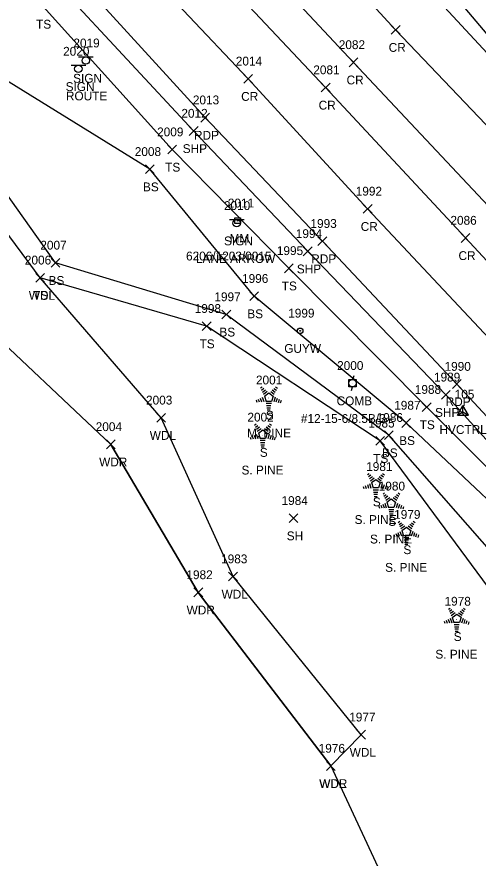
# Model space of a CAD drawing. Extents: x 1623612 to 1625808, y 621345 to 627748.
# Drawn here: x 1624252.1 to 1624356.5, y 626606.1 to 626796.7 of the extents above; entities that cross this region are included whole.
import ezdxf

# ---------------------------------------------------------------- set-up
doc = ezdxf.new("R2010")
doc.units = 0
for name, color, linetype in [('C_A', 7, 'Continuous'), ('C_I', 7, 'Continuous'), ('CPSM', 7, 'Continuous'), ('L_A', 7, 'Continuous'), ('L_C', 7, 'Continuous'), ('L_I', 7, 'Continuous'), ('L_TIC', 7, 'Continuous'), ('LAWA', 7, 'Continuous'), ('LELB', 7, 'Continuous'), ('LSOGP', 7, 'Continuous'), ('LTC', 7, 'Continuous'), ('P_A', 7, 'Continuous'), ('P_I', 7, 'Continuous'), ('P_TIC', 7, 'Continuous'), ('PET', 7, 'Continuous'), ('PRC', 7, 'Continuous'), ('PSP', 7, 'Continuous'), ('S_A', 7, 'Continuous'), ('S_C', 7, 'Continuous'), ('S_I', 7, 'Continuous'), ('SRM', 7, 'Continuous'), ('SSGN', 7, 'Continuous'), ('U_A', 7, 'Continuous'), ('U_C', 7, 'Continuous'), ('U_I', 7, 'Continuous'), ('UP', 7, 'Continuous'), ('UPGW', 7, 'Continuous')]:
    doc.layers.add(name, color=color, linetype=linetype)

msp = doc.modelspace()

# ---------------------------------------------------------------- linework, layer by layer
at = {"layer": 'CPSM'}
for p, q in [((1624351.85, 626706.52), (1624353.1, 626708.68)), ((1624354.35, 626706.52), (1624353.1, 626708.68)), ((1624353.1, 626707.24), (1624353.1, 626708.68)), ((1624351.85, 626706.52), (1624353.1, 626707.24)), ((1624351.85, 626706.52), (1624354.35, 626706.52)), ((1624353.1, 626707.24), (1624353.1, 626707.24)), ((1624353.1, 626707.24), (1624354.35, 626706.52))]:
    msp.add_line(p, q, dxfattribs=at)
at = {"layer": 'L_TIC'}
for points in [[(1624286.3, 626765.67), (1624288.3, 626767.67)], [(1624288.3, 626765.67), (1624286.3, 626767.67)], [(1624281.24, 626761.21), (1624283.24, 626763.21)], [(1624283.24, 626761.21), (1624281.24, 626763.21)], [(1624259.87, 626740.01), (1624261.87, 626742.01)], [(1624261.87, 626740.01), (1624259.87, 626742.01)], [(1624312.68, 626738.77), (1624314.68, 626740.77)], [(1624314.68, 626738.77), (1624312.68, 626740.77)], [(1624256.42, 626736.63), (1624258.42, 626738.63)], [(1624258.42, 626736.63), (1624256.42, 626738.63)], [(1624256.42, 626736.63), (1624258.42, 626738.63)], [(1624258.42, 626736.63), (1624256.42, 626738.63)], [(1624304.85, 626732.46), (1624306.85, 626734.46)], [(1624306.85, 626732.46), (1624304.85, 626734.46)], [(1624298.54, 626728.32), (1624300.54, 626730.32)], [(1624300.54, 626728.32), (1624298.54, 626730.32)], [(1624294.08, 626725.66), (1624296.08, 626727.66)], [(1624296.08, 626725.66), (1624294.08, 626727.66)], [(1624343.9, 626707.33), (1624345.9, 626709.33)], [(1624345.9, 626707.33), (1624343.9, 626709.33)], [(1624283.79, 626704.91), (1624285.79, 626706.91)], [(1624285.79, 626704.91), (1624283.79, 626706.91)], [(1624339.23, 626703.74), (1624341.23, 626705.74)], [(1624341.23, 626703.74), (1624339.23, 626705.74)], [(1624335.32, 626700.97), (1624337.32, 626702.97)], [(1624337.32, 626700.97), (1624335.32, 626702.97)], [(1624272.4, 626698.89), (1624274.4, 626700.89)], [(1624274.4, 626698.89), (1624272.4, 626700.89)], [(1624333.38, 626699.7), (1624335.38, 626701.7)], [(1624335.38, 626699.7), (1624333.38, 626701.7)], [(1624313.74, 626682.15), (1624315.74, 626684.15)], [(1624315.74, 626682.15), (1624313.74, 626684.15)], [(1624300.06, 626668.94), (1624302.06, 626670.94)], [(1624302.06, 626668.94), (1624300.06, 626670.94)], [(1624292.2, 626665.35), (1624294.2, 626667.35)], [(1624294.2, 626665.35), (1624292.2, 626667.35)], [(1624329.05, 626633.11), (1624331.05, 626635.11)], [(1624331.05, 626633.11), (1624329.05, 626635.11)], [(1624322.19, 626626.03), (1624324.19, 626628.03)], [(1624324.19, 626626.03), (1624322.19, 626628.03)], [(1624322.19, 626626.03), (1624324.19, 626628.03)], [(1624324.19, 626626.03), (1624322.19, 626628.03)]]:
    msp.add_lwpolyline(points, dxfattribs=at)
at = {"layer": 'LAWA'}
for points in [[(1624323.19, 626627.03), (1624330.05, 626634.11), (1624301.06, 626669.94), (1624284.79, 626705.91), (1624257.42, 626737.63), (1624223.02, 626784.04), (1624205.61, 626785.75)], [(1624323.19, 626627.03), (1624293.2, 626666.35), (1624273.4, 626699.89), (1624242.34, 626729.15), (1624205.61, 626785.75)]]:
    msp.add_lwpolyline(points, dxfattribs=at)
at = {"layer": 'LELB'}
for points in [[(1624382.88, 626625.35), (1624396.56, 626644.22), (1624396.84, 626651.57), (1624378.77, 626674.51), (1624344.9, 626708.33), (1624313.68, 626739.77), (1624287.3, 626766.67), (1624258.07, 626799.06), (1624230.36, 626827.29), (1624202.86, 626857.54), (1624181.4, 626879.71), (1624161.07, 626904.67)], [(1624380.03, 626635.67), (1624388.85, 626639.75), (1624394.9, 626646.05), (1624375.51, 626671.51), (1624340.23, 626704.74), (1624305.85, 626733.46), (1624282.24, 626762.21), (1624242, 626787.06), (1624227.53, 626819.4), (1624211.45, 626808.79)], [(1624388.85, 626639.75), (1624369.38, 626664.3), (1624336.32, 626701.97), (1624299.54, 626729.32), (1624260.87, 626741.01), (1624233.8, 626779.17), (1624211.45, 626808.79)], [(1624379.66, 626643.16), (1624364.81, 626659.38), (1624334.38, 626700.7), (1624295.08, 626726.66), (1624257.42, 626737.63)]]:
    msp.add_lwpolyline(points, dxfattribs=at)
at = {"layer": 'LSOGP'}
msp.add_lwpolyline([(1624185.05, 626801.31), (1624205.61, 626785.75), (1624242.34, 626729.15), (1624273.4, 626699.89), (1624293.2, 626666.35), (1624323.19, 626627.03), (1624337.94, 626595.4), (1624375.16, 626557.28)], dxfattribs=at)
at = {"layer": 'LTC'}
for p, q in [((1624307.29, 626712.67), (1624307.65, 626712.93)), ((1624307.5, 626712.2), (1624308.03, 626712.59)), ((1624307.71, 626711.74), (1624308.42, 626712.25)), ((1624307.92, 626711.27), (1624308.8, 626711.91)), ((1624309.58, 626711.86), (1624310.39, 626711.27)), ((1624309.95, 626712.21), (1624310.63, 626711.72)), ((1624310.32, 626712.56), (1624310.87, 626712.16)), ((1624310.69, 626712.91), (1624311.11, 626712.6)), ((1624306.33, 626709.95), (1624306.48, 626709.48)), ((1624306.78, 626710.16), (1624306.99, 626709.51)), ((1624307.24, 626710.38), (1624307.51, 626709.54)), ((1624307.69, 626710.6), (1624308.02, 626709.58)), ((1624308.15, 626710.82), (1624309.16, 626711.55)), ((1624308.15, 626710.82), (1624308.53, 626709.62)), ((1624309.16, 626711.55), (1624310.16, 626710.83)), ((1624310.16, 626710.83), (1624309.76, 626709.62)), ((1624310.59, 626710.55), (1624310.26, 626709.51)), ((1624311.04, 626710.3), (1624310.75, 626709.42)), ((1624311.48, 626710.05), (1624311.25, 626709.32)), ((1624309.76, 626709.62), (1624308.53, 626709.62)), ((1624309.73, 626709.12), (1624308.58, 626709.12)), ((1624309.64, 626708.62), (1624308.65, 626708.62)), ((1624309.56, 626708.12), (1624308.73, 626708.12)), ((1624311.93, 626709.8), (1624311.74, 626709.23)), ((1624309.48, 626707.62), (1624308.8, 626707.62)), ((1624305.93, 626704.27), (1624306.29, 626704.53)), ((1624306.14, 626703.81), (1624306.67, 626704.19)), ((1624309.33, 626704.51), (1624309.75, 626704.21)), ((1624306.35, 626703.34), (1624307.06, 626703.85)), ((1624306.56, 626702.87), (1624307.44, 626703.51)), ((1624306.79, 626702.42), (1624307.8, 626703.15)), ((1624306.79, 626702.42), (1624307.17, 626701.23)), ((1624307.8, 626703.15), (1624308.8, 626702.43)), ((1624308.22, 626703.47), (1624309.03, 626702.88)), ((1624308.8, 626702.43), (1624308.4, 626701.23)), ((1624308.59, 626703.82), (1624309.27, 626703.32)), ((1624308.96, 626704.16), (1624309.51, 626703.76)), ((1624304.97, 626701.55), (1624305.12, 626701.08)), ((1624305.42, 626701.77), (1624305.63, 626701.12)), ((1624305.88, 626701.98), (1624306.15, 626701.15)), ((1624306.33, 626702.2), (1624306.66, 626701.18)), ((1624308.4, 626701.23), (1624307.17, 626701.23)), ((1624308.37, 626700.73), (1624307.22, 626700.73)), ((1624309.23, 626702.16), (1624308.9, 626701.12)), ((1624309.68, 626701.91), (1624309.39, 626701.02)), ((1624310.12, 626701.66), (1624309.89, 626700.93)), ((1624310.57, 626701.41), (1624310.38, 626700.83)), ((1624308.28, 626700.23), (1624307.29, 626700.23)), ((1624308.2, 626699.73), (1624307.37, 626699.73)), ((1624308.11, 626699.23), (1624307.44, 626699.23)), ((1624331.52, 626693.06), (1624331.87, 626693.32)), ((1624331.73, 626692.59), (1624332.26, 626692.98)), ((1624334.54, 626692.95), (1624335.09, 626692.55)), ((1624334.92, 626693.3), (1624335.33, 626692.99)), ((1624331.92, 626690.99), (1624332.25, 626689.97)), ((1624331.94, 626692.13), (1624332.64, 626692.64)), ((1624332.15, 626691.66), (1624333.02, 626692.3)), ((1624332.37, 626691.21), (1624333.38, 626691.94)), ((1624332.37, 626691.21), (1624332.76, 626690.01)), ((1624333.38, 626691.94), (1624334.38, 626691.22)), ((1624333.8, 626692.25), (1624334.61, 626691.66)), ((1624334.38, 626691.22), (1624333.99, 626690.01)), ((1624334.17, 626692.6), (1624334.85, 626692.11)), ((1624334.82, 626690.94), (1624334.48, 626689.9)), ((1624330.55, 626690.34), (1624330.7, 626689.87)), ((1624331, 626690.55), (1624331.22, 626689.9)), ((1624331.46, 626690.77), (1624331.73, 626689.93)), ((1624333.99, 626690.01), (1624332.76, 626690.01)), ((1624333.95, 626689.51), (1624332.8, 626689.51)), ((1624333.87, 626689.01), (1624332.88, 626689.01)), ((1624335.26, 626690.69), (1624334.97, 626689.81)), ((1624335.71, 626690.44), (1624335.47, 626689.71)), ((1624336.15, 626690.19), (1624335.96, 626689.62)), ((1624333.78, 626688.51), (1624332.95, 626688.51)), ((1624333.7, 626688.01), (1624333.02, 626688.01)), ((1624335.01, 626688.63), (1624335.37, 626688.89)), ((1624335.22, 626688.17), (1624335.75, 626688.55)), ((1624335.43, 626687.7), (1624336.13, 626688.21)), ((1624335.64, 626687.24), (1624336.52, 626687.87)), ((1624335.87, 626686.78), (1624336.88, 626687.52)), ((1624336.88, 626687.52), (1624337.87, 626686.79)), ((1624337.3, 626687.83), (1624338.11, 626687.24)), ((1624337.67, 626688.18), (1624338.35, 626687.68)), ((1624338.04, 626688.53), (1624338.59, 626688.13)), ((1624338.41, 626688.87), (1624338.83, 626688.57)), ((1624334.04, 626685.91), (1624334.2, 626685.44)), ((1624334.5, 626686.13), (1624334.71, 626685.48)), ((1624334.96, 626686.35), (1624335.23, 626685.51)), ((1624335.41, 626686.56), (1624335.74, 626685.54)), ((1624335.87, 626686.78), (1624336.25, 626685.59)), ((1624337.48, 626685.59), (1624336.25, 626685.59)), ((1624337.87, 626686.79), (1624337.48, 626685.59)), ((1624338.31, 626686.52), (1624337.97, 626685.48)), ((1624338.76, 626686.27), (1624338.47, 626685.39)), ((1624339.2, 626686.02), (1624338.96, 626685.29)), ((1624339.64, 626685.77), (1624339.46, 626685.2)), ((1624337.44, 626685.09), (1624336.3, 626685.09)), ((1624337.36, 626684.59), (1624336.37, 626684.59)), ((1624337.28, 626684.09), (1624336.45, 626684.09)), ((1624337.19, 626683.59), (1624336.52, 626683.59)), ((1624338.43, 626682.22), (1624338.78, 626682.48)), ((1624338.64, 626681.76), (1624339.17, 626682.14)), ((1624338.85, 626681.29), (1624339.55, 626681.8)), ((1624339.06, 626680.83), (1624339.94, 626681.46)), ((1624340.71, 626681.42), (1624341.52, 626680.83)), ((1624341.09, 626681.77), (1624341.76, 626681.27)), ((1624341.46, 626682.12), (1624342.01, 626681.72)), ((1624341.83, 626682.46), (1624342.25, 626682.16)), ((1624337.46, 626679.5), (1624337.61, 626679.03)), ((1624337.92, 626679.72), (1624338.13, 626679.07)), ((1624338.37, 626679.94), (1624338.64, 626679.1)), ((1624338.83, 626680.15), (1624339.16, 626679.13)), ((1624339.28, 626680.37), (1624340.29, 626681.11)), ((1624339.28, 626680.37), (1624339.67, 626679.18)), ((1624340.29, 626681.11), (1624341.29, 626680.38)), ((1624341.29, 626680.38), (1624340.9, 626679.18)), ((1624341.73, 626680.11), (1624341.39, 626679.07)), ((1624342.17, 626679.86), (1624341.89, 626678.98)), ((1624342.62, 626679.61), (1624342.38, 626678.88)), ((1624340.9, 626679.18), (1624339.67, 626679.18)), ((1624340.86, 626678.68), (1624339.72, 626678.68)), ((1624340.78, 626678.18), (1624339.79, 626678.18)), ((1624340.69, 626677.68), (1624339.86, 626677.68)), ((1624343.06, 626679.36), (1624342.88, 626678.79)), ((1624340.61, 626677.18), (1624339.94, 626677.18)), ((1624349.82, 626662.55), (1624350.17, 626662.81)), ((1624350.03, 626662.08), (1624350.55, 626662.47)), ((1624352.84, 626662.44), (1624353.39, 626662.04)), ((1624353.21, 626662.79), (1624353.63, 626662.48)), ((1624350.21, 626660.48), (1624350.55, 626659.46)), ((1624350.24, 626661.62), (1624350.94, 626662.13)), ((1624350.44, 626661.15), (1624351.32, 626661.79)), ((1624350.67, 626660.7), (1624351.68, 626661.43)), ((1624350.67, 626660.7), (1624351.06, 626659.5)), ((1624351.68, 626661.43), (1624352.68, 626660.71)), ((1624352.1, 626661.74), (1624352.91, 626661.16)), ((1624352.68, 626660.71), (1624352.29, 626659.5)), ((1624352.47, 626662.09), (1624353.15, 626661.6)), ((1624353.12, 626660.44), (1624352.78, 626659.4)), ((1624348.85, 626659.83), (1624349, 626659.36)), ((1624349.3, 626660.04), (1624349.52, 626659.39)), ((1624349.76, 626660.26), (1624350.03, 626659.43)), ((1624352.29, 626659.5), (1624351.06, 626659.5)), ((1624352.25, 626659), (1624351.1, 626659)), ((1624352.16, 626658.5), (1624351.18, 626658.5)), ((1624353.56, 626660.19), (1624353.27, 626659.3)), ((1624354, 626659.94), (1624353.77, 626659.21)), ((1624354.45, 626659.68), (1624354.26, 626659.11)), ((1624352.08, 626658), (1624351.25, 626658)), ((1624352, 626657.5), (1624351.32, 626657.5))]:
    msp.add_line(p, q, dxfattribs=at)
at = {"layer": 'P_TIC'}
for points in [[(1624336.86, 626792.81), (1624338.86, 626794.81)], [(1624338.86, 626792.81), (1624336.86, 626794.81)], [(1624327.33, 626785.43), (1624329.33, 626787.43)], [(1624329.33, 626785.43), (1624327.33, 626787.43)], [(1624303.47, 626781.71), (1624305.47, 626783.71)], [(1624305.47, 626781.71), (1624303.47, 626783.71)], [(1624321.01, 626779.73), (1624323.01, 626781.73)], [(1624323.01, 626779.73), (1624321.01, 626781.73)], [(1624293.74, 626772.91), (1624295.74, 626774.91)], [(1624295.74, 626772.91), (1624293.74, 626774.91)], [(1624291.14, 626769.88), (1624293.14, 626771.88)], [(1624293.14, 626769.88), (1624291.14, 626771.88)], [(1624330.53, 626752.24), (1624332.53, 626754.24)], [(1624332.53, 626752.24), (1624330.53, 626754.24)], [(1624320.29, 626744.92), (1624322.29, 626746.92)], [(1624322.29, 626744.92), (1624320.29, 626746.92)], [(1624352.66, 626745.64), (1624354.66, 626747.64)], [(1624354.66, 626745.64), (1624352.66, 626747.64)], [(1624316.97, 626742.62), (1624318.97, 626744.62)], [(1624318.97, 626742.62), (1624316.97, 626744.62)], [(1624350.7, 626712.55), (1624352.7, 626714.55)], [(1624352.7, 626712.55), (1624350.7, 626714.55)], [(1624348.24, 626710.12), (1624350.24, 626712.12)], [(1624350.24, 626710.12), (1624348.24, 626712.12)]]:
    msp.add_lwpolyline(points, dxfattribs=at)
at = {"layer": 'PET'}
for points in [[(1624211.36, 626948.94), (1624238.72, 626919.55), (1624262.36, 626893.71), (1624286.05, 626868.28), (1624309.88, 626842.73), (1624340.2, 626808.47), (1624365.34, 626781.16), (1624395.18, 626750.47), (1624419.59, 626724.64), (1624445.91, 626697.02), (1624473.1, 626668.14), (1624507.26, 626632.06), (1624527.99, 626609.86), (1624550.6, 626585.36), (1624578.26, 626556.05), (1624603.3, 626530.62), (1624620.59, 626513.39), (1624649.07, 626495.66), (1624671.18, 626489.46), (1624702.74, 626490.16)], [(1624682.54, 626327.48), (1624678.38, 626346.43), (1624673.34, 626359.16), (1624665.22, 626373.75), (1624654.29, 626387.74), (1624639.33, 626403.95), (1624606.52, 626439.12), (1624581.34, 626466.22), (1624553.07, 626496.91), (1624531.24, 626520.29), (1624503.05, 626550.6), (1624469.83, 626586.28), (1624436.59, 626622.29), (1624410.08, 626650.63), (1624383.72, 626678.98), (1624351.7, 626713.55), (1624321.29, 626745.92), (1624294.74, 626773.91), (1624265.91, 626805.6)]]:
    msp.add_lwpolyline(points, dxfattribs=at)
at = {"layer": 'PRC'}
for points in [[(1624202.38, 626941), (1624231.95, 626909.33), (1624268.3, 626868.91), (1624305.54, 626828.99), (1624337.86, 626793.81), (1624369.19, 626760.84), (1624403.29, 626724.16), (1624436.76, 626689.12), (1624471.08, 626653.03), (1624500.99, 626619.01), (1624533.46, 626585.06), (1624572.18, 626543.82), (1624598.35, 626515.6), (1624627.03, 626484.27), (1624657.97, 626450.75), (1624685.1, 626421.27), (1624710.89, 626393.93)], [(1624192.12, 626932.46), (1624222.52, 626900.06), (1624257.95, 626861.76), (1624296.14, 626820.93), (1624328.33, 626786.43), (1624360.02, 626752.63), (1624393.53, 626716.71), (1624427.43, 626680.74), (1624459.98, 626645.81), (1624494.27, 626609.22)], [(1624186.13, 626926.24), (1624216.09, 626894.04), (1624252.24, 626855.54), (1624289.91, 626814.88), (1624322.01, 626780.73), (1624353.66, 626746.64), (1624386.67, 626711.08), (1624421.34, 626674.27), (1624454.07, 626638.87), (1624487.99, 626602.6), (1624516.65, 626571.23)], [(1624691.43, 626366.48), (1624669.78, 626388.58), (1624647.94, 626412.24), (1624616.12, 626446.54), (1624589.59, 626475.6), (1624562.81, 626504.24), (1624540.57, 626528.3), (1624511.37, 626559.76), (1624478.76, 626595.67), (1624444.94, 626631.16), (1624418.89, 626658.65), (1624393.01, 626686.5), (1624360.17, 626722.63), (1624331.53, 626753.24), (1624304.47, 626782.71), (1624275.06, 626813.9), (1624246.4, 626843.61), (1624219.02, 626871.9), (1624198.62, 626894.75), (1624176.28, 626917.84)]]:
    msp.add_lwpolyline(points, dxfattribs=at)
at = {"layer": 'PSP'}
for points in [[(1624213.53, 626951.11), (1624241.13, 626921.37), (1624264.77, 626895.8), (1624288.11, 626870.32), (1624312.07, 626845.04), (1624343.91, 626810.12), (1624367.27, 626782.46), (1624384.8, 626765.81), (1624396.96, 626752.53), (1624422.27, 626726.83), (1624449.32, 626699.43), (1624476.73, 626671.47), (1624511.72, 626635.98), (1624532.99, 626613.93), (1624555.81, 626591.77), (1624557.1, 626590.85), (1624584.71, 626562.13), (1624609.17, 626536.98), (1624624.05, 626517.59), (1624651.19, 626501.54), (1624672.81, 626495.1), (1624698.38, 626495.38)], [(1624676.55, 626327.48), (1624673.72, 626344.86), (1624670.58, 626356.08), (1624664.11, 626370.71), (1624652.39, 626385.59), (1624636.52, 626401.6), (1624603.46, 626436.72), (1624579, 626463.66), (1624550.01, 626494.21), (1624528.45, 626517.8), (1624500.38, 626548.3), (1624466.85, 626583.85), (1624433.64, 626619.4), (1624408.06, 626646.48), (1624380.64, 626676.32), (1624349.24, 626711.12), (1624317.97, 626743.62), (1624292.14, 626770.88), (1624262.1, 626803.32)]]:
    msp.add_lwpolyline(points, dxfattribs=at)
at = {"layer": 'SRM'}
msp.add_lwpolyline([(1624301.47, 626751.18), (1624302.72, 626751.18), (1624302.72, 626749.93), (1624301.47, 626749.93)], close=True, dxfattribs=at)
msp.add_circle((1624302.1, 626750.55), 0.0833, dxfattribs=at)
at = {"layer": 'SSGN'}
for p, q in [((1624266.09, 626787.67), (1624269.42, 626787.67)), ((1624267.73, 626786.83), (1624267.73, 626786.83)), ((1624264.4, 626785.79), (1624267.73, 626785.79)), ((1624266.05, 626784.95), (1624266.05, 626784.95)), ((1624300.23, 626750.82), (1624303.57, 626750.82)), ((1624301.88, 626749.99), (1624301.88, 626749.99))]:
    msp.add_line(p, q, dxfattribs=at)
for centre in [(1624267.73, 626786.83), (1624266.05, 626784.95), (1624301.88, 626749.99)]:
    msp.add_circle(centre, 0.833, dxfattribs=at)
at = {"layer": 'UP'}
for p, q in [((1624327.29, 626712.9), (1624327.29, 626714.57)), ((1624327.29, 626714.57), (1624328.95, 626714.57)), ((1624328.37, 626715.4), (1624328.12, 626714.57)), ((1624328.12, 626713.74), (1624328.12, 626713.74)), ((1624328.95, 626714.57), (1624328.95, 626712.9)), ((1624328.95, 626712.9), (1624327.29, 626712.9)), ((1624327.87, 626712.07), (1624328.12, 626712.9))]:
    msp.add_line(p, q, dxfattribs=at)
msp.add_circle((1624328.12, 626713.74), 0.833, dxfattribs=at)
at = {"layer": 'UPGW'}
for radius in [0.625, 0.0833]:
    msp.add_circle((1624316.25, 626725.61), radius, dxfattribs=at)

# ---------------------------------------------------------------- texts
at = {"layer": 'C_A'}
msp.add_text('HVCTRL', height=2, dxfattribs=at).set_placement((1624347.79, 626702.24))
at = {"layer": 'C_I'}
msp.add_text('105', height=2, dxfattribs=at).set_placement((1624351.23, 626710.24))
at = {"layer": 'L_A'}
for s, p in [('TS', (1624256.48, 626794.06)), ('TS', (1624285.71, 626761.67)), ('BS', (1624280.68, 626757.21)), ('BS', (1624259.31, 626736.01)), ('TS', (1624312.09, 626734.77)), ('WDL', (1624254.84, 626732.63)), ('TS', (1624255.83, 626732.63)), ('BS', (1624304.29, 626728.46)), ('BS', (1624297.98, 626724.32)), ('TS', (1624293.49, 626721.66)), ('S', (1624308.48, 626705.46)), ('TS', (1624343.31, 626703.33)), ('WDL', (1624282.21, 626700.91)), ('BS', (1624338.67, 626699.74)), ('S', (1624307.12, 626697.06)), ('BS', (1624334.76, 626696.97)), ('WDR', (1624270.76, 626694.89)), ('TS', (1624332.79, 626695.7)), ('S', (1624332.71, 626685.85)), ('S', (1624336.2, 626681.43)), ('SH', (1624313.22, 626678.15)), ('S', (1624339.62, 626675.02)), ('WDL', (1624298.47, 626664.94)), ('WDR', (1624290.56, 626661.35)), ('S', (1624351.01, 626655.34)), ('WDL', (1624327.47, 626629.11)), ('WDR', (1624320.55, 626622.03)), ('WDL', (1624320.6, 626622.03))]:
    msp.add_text(s, height=2, dxfattribs=at).set_placement(p)
at = {"layer": 'L_C'}
for s, p in [('M. PINE', (1624304.22, 626701.46)), ('S. PINE', (1624302.98, 626693.06)), ('S. PINE', (1624328.57, 626681.85)), ('S. PINE', (1624332.06, 626677.43)), ('S. PINE', (1624335.48, 626671.02)), ('S. PINE', (1624346.86, 626651.34))]:
    msp.add_text(s, height=2, dxfattribs=at).set_placement(p)
at = {"layer": 'L_I'}
for s, p in [('2009', (1624283.88, 626769.67)), ('2008', (1624278.82, 626765.21)), ('2007', (1624257.45, 626744.01)), ('1995', (1624310.98, 626742.77)), ('2006', (1624253.95, 626740.63)), ('2006', (1624253.95, 626740.63)), ('1996', (1624303.1, 626736.46)), ('1997', (1624296.84, 626732.32)), ('1998', (1624292.39, 626729.66)), ('2001', (1624306.25, 626713.46)), ('1988', (1624342.2, 626711.33)), ('2003', (1624281.37, 626708.91)), ('1987', (1624337.54, 626707.74)), ('2002', (1624304.32, 626705.06)), ('1986', (1624333.57, 626704.97)), ('2004', (1624269.98, 626702.89)), ('1985', (1624331.69, 626703.7)), ('1981', (1624331.2, 626693.85)), ('1980', (1624334.04, 626689.43)), ('1984', (1624312.04, 626686.15)), ('1979', (1624337.53, 626683.02)), ('1983', (1624298.36, 626672.94)), ('1982', (1624290.51, 626669.35)), ('1978', (1624348.93, 626663.34)), ('1977', (1624327.36, 626637.11)), ('1976', (1624320.44, 626630.03)), ('1976', (1624320.44, 626630.03))]:
    msp.add_text(s, height=2, dxfattribs=at).set_placement(p)
at = {"layer": 'LTC'}
for p in [(1624309.04, 626710.56), (1624307.68, 626702.17), (1624333.26, 626690.95), (1624336.76, 626686.53), (1624340.18, 626680.12), (1624351.56, 626660.44)]:
    msp.add_text('.', height=1.04, rotation=270, dxfattribs=at).set_placement(p)
at = {"layer": 'P_A'}
for s, p in [('CR', (1624336.29, 626788.81)), ('CR', (1624326.76, 626781.43)), ('CR', (1624302.9, 626777.71)), ('CR', (1624320.44, 626775.73)), ('RDP', (1624292.23, 626768.91)), ('SHP', (1624289.67, 626765.88)), ('CR', (1624329.96, 626748.24)), ('RDP', (1624318.77, 626740.92)), ('CR', (1624352.09, 626741.64)), ('SHP', (1624315.5, 626738.62)), ('RDP', (1624349.19, 626708.55)), ('SHP', (1624346.78, 626706.12))]:
    msp.add_text(s, height=2, dxfattribs=at).set_placement(p)
at = {"layer": 'P_I'}
for s, p in [('2082', (1624324.99, 626789.43)), ('2014', (1624301.69, 626785.71)), ('2081', (1624319.23, 626783.73)), ('2013', (1624291.97, 626776.91)), ('2012', (1624289.37, 626773.88)), ('1992', (1624328.83, 626756.24)), ('1993', (1624318.59, 626748.92)), ('2086', (1624350.26, 626749.64)), ('1994', (1624315.27, 626746.62)), ('1990', (1624348.93, 626716.55)), ('1989', (1624346.54, 626714.12))]:
    msp.add_text(s, height=2, dxfattribs=at).set_placement(p)
at = {"layer": 'S_A'}
for s, p in [('SIGN', (1624264.87, 626781.81)), ('SIGN', (1624263.18, 626779.93)), ('SIGN', (1624299.02, 626744.97)), ('MM', (1624300.29, 626745.55))]:
    msp.add_text(s, height=2, dxfattribs=at).set_placement(p)
at = {"layer": 'S_C'}
for s, p in [('ROUTE', (1624263.24, 626777.81)), ('6206/1203/0015', (1624290.43, 626741.55)), ('LANE ARROW', (1624292.66, 626740.97))]:
    msp.add_text(s, height=2, dxfattribs=at).set_placement(p)
at = {"layer": 'S_I'}
for s, p in [('2020', (1624262.6, 626787.93)), ('2019', (1624264.93, 626789.81)), ('2010', (1624299, 626752.97)), ('2011', (1624299.89, 626753.55))]:
    msp.add_text(s, height=2, dxfattribs=at).set_placement(p)
at = {"layer": 'U_A'}
for s, p in [('GUYW', (1624312.65, 626720.61)), ('COMB', (1624324.51, 626708.74))]:
    msp.add_text(s, height=2, dxfattribs=at).set_placement(p)
at = {"layer": 'U_C'}
msp.add_text('#12-15-6/8.5B/3', height=2, dxfattribs=at).set_placement((1624316.43, 626704.74))
at = {"layer": 'U_I'}
for s, p in [('1999', (1624313.55, 626728.61)), ('2000', (1624324.62, 626716.74))]:
    msp.add_text(s, height=2, dxfattribs=at).set_placement(p)

doc.saveas('drawing.dxf')
